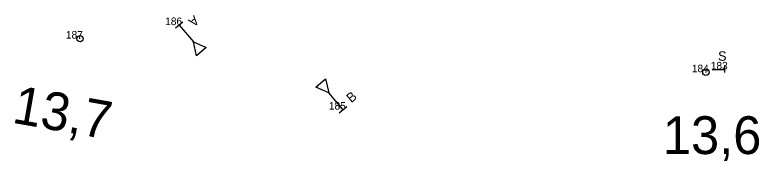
# Model space of a CAD drawing. Extents: x -554814 to -554052, y -1115925 to -1115523.
# Drawn here: x -554170 to -554051.9, y -1115924.7 to -1115901.4 of the extents above; entities that cross this region are included whole.
import ezdxf

# ---------------------------------------------------------------- set-up
doc = ezdxf.new("R2010")
doc.units = 0
for name, color, linetype in [('Vrstva 4', 7, 'Continuous'), ('Vrstva 6', 7, 'Continuous'), ('Vrstva 60', 7, 'Continuous'), ('Vrstva 7', 7, 'Continuous')]:
    doc.layers.add(name, color=color, linetype=linetype)

msp = doc.modelspace()

# ---------------------------------------------------------------- linework, layer by layer
at = {"layer": 'Vrstva 4'}
for p, q in [((-554143.29, -1115902.58), (-554144.48, -1115903.57)), ((-554118.51, -1115916.98), (-554117.31, -1115915.98))]:
    msp.add_line(p, q, dxfattribs=at)
for points in [[(-554143.88, -1115903.07), (-554141.65, -1115905.74), (-554139.61, -1115906.64), (-554141.13, -1115907.93), (-554141.65, -1115905.74)], [(-554117.91, -1115916.48), (-554120.14, -1115913.81), (-554122.19, -1115912.91), (-554120.66, -1115911.62), (-554120.14, -1115913.81)]]:
    msp.add_lwpolyline(points, dxfattribs=at)
at = {"layer": 'Vrstva 6'}
for p, q in [((-554057.32, -1115910.61), (-554057.32, -1115909.61)), ((-554059.31, -1115910.11), (-554057.32, -1115910.11))]:
    msp.add_line(p, q, dxfattribs=at)
at = {"layer": 'Vrstva 60'}
for p, q in [((-554143.88, -1115903.07), (-554143.88, -1115903.07)), ((-554159.63, -1115905.21), (-554159.63, -1115905.21)), ((-554060.33, -1115910.55), (-554060.33, -1115910.55)), ((-554057.32, -1115910.11), (-554057.32, -1115910.11)), ((-554117.91, -1115916.48), (-554117.91, -1115916.48))]:
    msp.add_line(p, q, dxfattribs=at)
at = {"layer": 'Vrstva 7'}
for p, q in [((-554159.58, -1115905.23), (-554159.68, -1115905.19)), ((-554060.28, -1115910.55), (-554060.38, -1115910.55))]:
    msp.add_line(p, q, dxfattribs=at)
for centre in [(-554159.63, -1115905.21), (-554060.33, -1115910.55)]:
    msp.add_circle(centre, 0.5, dxfattribs=at)

# ---------------------------------------------------------------- texts
at = {"layer": 'Vrstva 4'}
for s, rotation, p in [('A', 220, (-554141.54, -1115901.45)), ('B', 40, (-554116.59, -1115915.48))]:
    msp.add_text(s, height=1.5, rotation=rotation, dxfattribs=at).set_placement(p)
at = {"layer": 'Vrstva 6'}
msp.add_text('S', height=1.5, dxfattribs=at).set_placement((-554058.39, -1115908.73))
at = {"layer": 'Vrstva 60'}
for s, p in [('186', (-554146.11, -1115903.07)), ('187', (-554161.86, -1115905.21)), ('184', (-554062.55, -1115910.55)), ('183', (-554059.55, -1115910.11)), ('185', (-554120.14, -1115916.48))]:
    msp.add_text(s, height=1.2, dxfattribs=at).set_placement(p)
at = {"layer": 'Vrstva 7'}
msp.add_text('13,7', height=6, rotation=350, dxfattribs=at).set_placement((-554170.56, -1115918.54))
msp.add_text('13,6', height=6, dxfattribs=at).set_placement((-554067.15, -1115923.54))

doc.saveas('drawing.dxf')
